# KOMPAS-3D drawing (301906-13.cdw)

Views: Вид 1, Вид 2
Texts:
  Крышка люка
  денис
  Текст на чертеже
  Размерные надписи
  Шероховатость
  Линия-выноска #1
  Линия-выноска #2
  Линия-выноска #3
  Отклонения формы и база
  Заголовок таблицы
  Ячейка таблицы
  Стрелка вида
  Обозначение изменения
  Фигурная скобка
  Номер узла
  Марка координационной оси
  VRCB
  Выносная надпись
  Обозначение узла
  Марка/позиционное обозначение с линией-выноской
  Марка/позиционное обозначение на линии
  Марка/позиционное обозначение без линии-выноски
  ГОСТ 5632-72-Т6
  Технические требования
  1. После сварки неровности зачистить с плавным переходом к основному металлу.
  2. Сварные швы подлежат контролю качества соединений
  Ручка
  Крышка
  Баранов Д.А.
  СПБГТИ(ТУ)
  гр.364
Dimensions and other numbers on the sheet: 105.16.03.00.000СБ; 7; 17; 26; 620; 543; 446; 23; 20 отв.; 197; 16; 580; 96; 70; 1; 2; 05.16.03.00.001; 05.16.03.00.002; 1:2; 105.16.03.00.000СБ-; 0; 3; 4; 5; 6; 8; 9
